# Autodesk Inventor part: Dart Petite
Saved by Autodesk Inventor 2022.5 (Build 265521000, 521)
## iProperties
Created: 2025-02
Part Number: Dart Petite
Material: Generic
Document SubType Name: Modeling
Designer: AdminForWorker
Density: 1 g/cm^3
Appearance: Default
Title: Dart Petite
Author: AdminForWorker
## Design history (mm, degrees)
feature "Dart Petite"
body "Solid1"
